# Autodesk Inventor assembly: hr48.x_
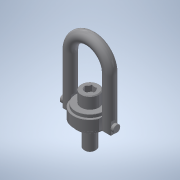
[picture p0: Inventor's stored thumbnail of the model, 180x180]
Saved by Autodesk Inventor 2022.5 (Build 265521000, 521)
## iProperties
Part Number: hr48.x_
Material: 一般
Document SubType Name: Assembly
Designer: ImaoCorp
Sending System: SOLIDWORKS 2017-2017317
MC: AMD64
MC_MODEL: Intel64 Family 6 Model 60 Stepping 3, GenuineIntel
OS: Windows_NT
FRU: Parasolid Version 29.0, build 201,  4-17-2017
FORMAT: text
GUISE: transmit
KEY: hr48
FILE: hr48.x_t
DATE: Mon Jul 01 17:38:31 2019
Author: ImaoCorp
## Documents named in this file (3)
- X:\14_SW2022-Inv2022\00_全2023-1023新製品(TCC)まで\h\hr48\HR48.iam
- X:\14_SW2022-Inv2022\00_全2023-1023新製品(TCC)まで\h\hr48\hr48_01.ipt
- X:\14_SW2022-Inv2022\00_全2023-1023新製品(TCC)まで\h\hr48\hr48_02.ipt
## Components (2 placed, 2 different names)
1. hr48_01
2. hr48_02
